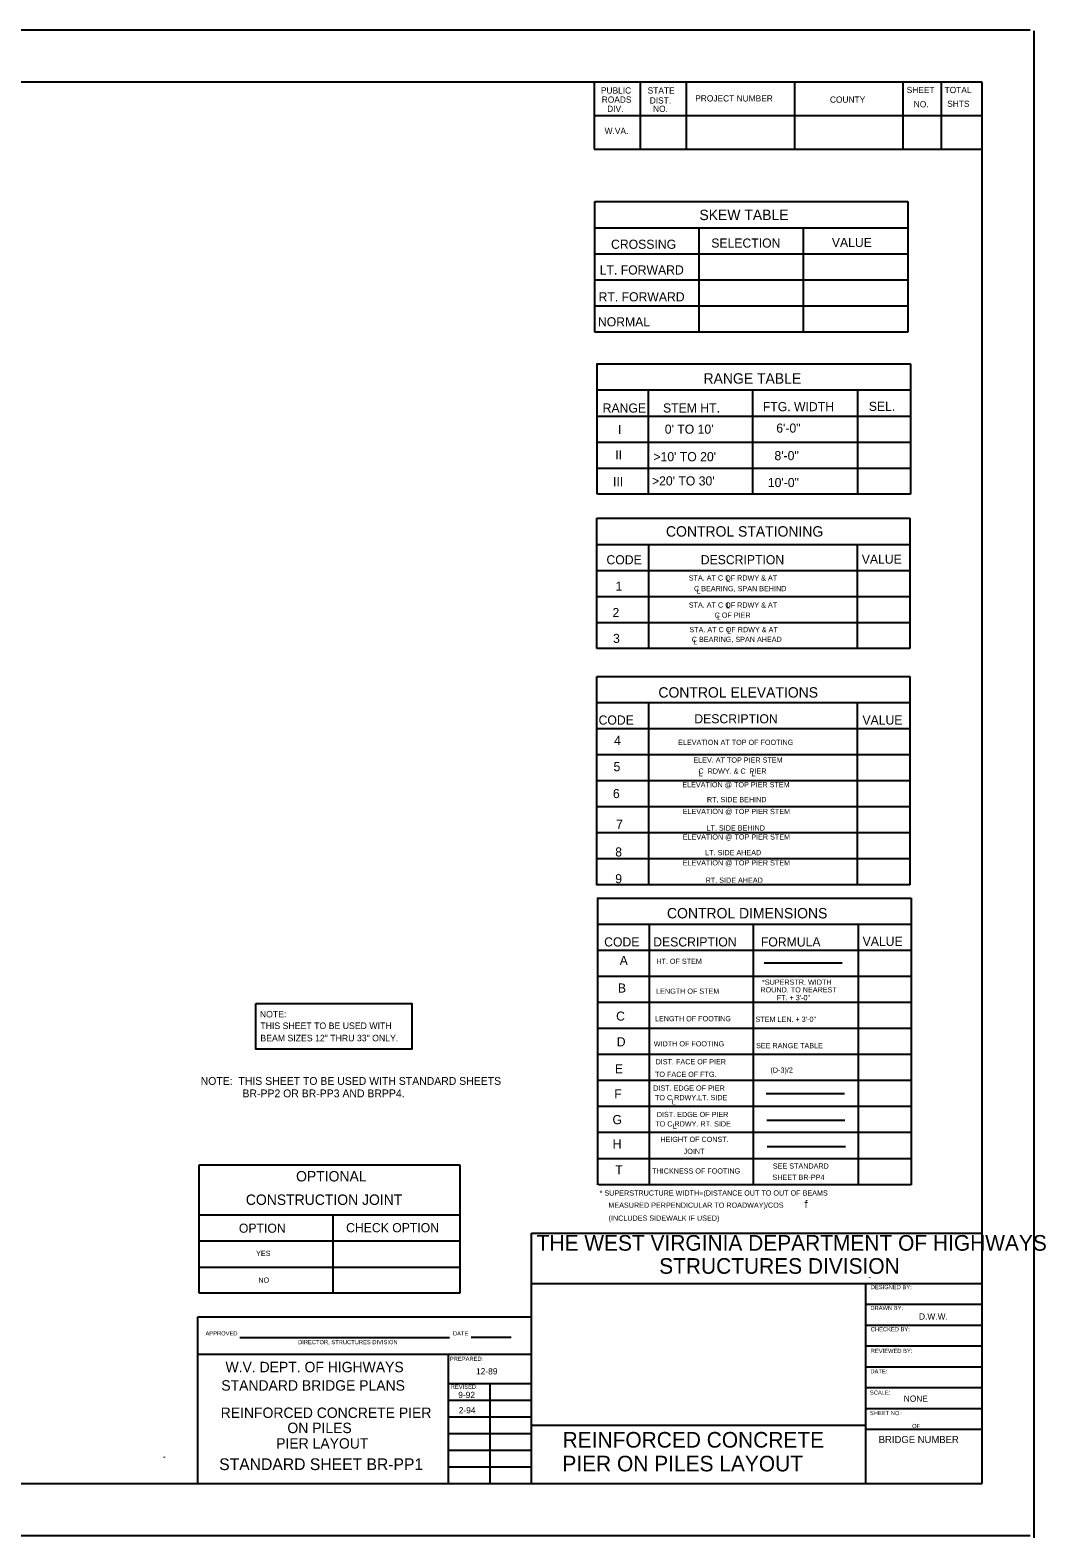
# Model space of a CAD drawing. Extents: x 1.6 to 6.29, y 2.8 to 7.08.
# Drawn here: x 4.663 to 6.287, y 4.671 to 7.081 of the extents above; entities that cross this region are included whole.
import ezdxf

# ---------------------------------------------------------------- set-up
doc = ezdxf.new("R2010")
doc.units = 0
doc.layers.add('Level 1', color=7, linetype='Continuous')
doc.layers.add('Level 5', color=7, linetype='Continuous')

msp = doc.modelspace()

# ---------------------------------------------------------------- linework, layer by layer
at = {"layer": 'Level 1'}
for p, q in [((6.2614, 7.0813), (2.3914, 7.0813)), ((6.2681, 4.6712), (6.2681, 7.0801)), ((6.1848, 6.998), (2.5581, 6.998)), ((5.5648, 6.998), (5.5648, 6.8913)), ((5.6381, 6.998), (5.6381, 6.8913)), ((5.7114, 6.998), (5.7114, 6.8913)), ((5.8847, 6.998), (5.8847, 6.8913)), ((6.0581, 6.998), (6.0581, 6.8913)), ((6.1194, 6.998), (6.1194, 6.8913)), ((6.1848, 4.758), (6.1848, 6.998)), ((5.5648, 6.9447), (6.1848, 6.9447)), ((5.5648, 6.8913), (6.1848, 6.8913)), ((5.5658, 6.5988), (5.5658, 6.8072)), ((5.5658, 6.8072), (6.0658, 6.8072)), ((6.0658, 6.8072), (6.0658, 6.5988)), ((5.5658, 6.7655), (6.0658, 6.7655)), ((5.7325, 6.5988), (5.7325, 6.7662)), ((5.8992, 6.5988), (5.8992, 6.7652)), ((5.5658, 6.7238), (6.0658, 6.7238)), ((5.5658, 6.6822), (6.0658, 6.6822)), ((5.5658, 6.6405), (6.0658, 6.6405)), ((6.0658, 6.5988), (5.5658, 6.5988)), ((5.5681, 6.5478), (6.0681, 6.5478)), ((5.5692, 6.3397), (5.5692, 6.548)), ((5.57, 6.5478), (6.07, 6.5478)), ((6.07, 6.5478), (6.07, 6.3395)), ((5.57, 6.5062), (6.07, 6.5062)), ((5.6515, 6.3397), (5.6515, 6.5061)), ((5.8182, 6.3403), (5.8182, 6.5066)), ((5.9859, 6.3397), (5.9859, 6.5061)), ((5.57, 6.4645), (6.07, 6.4645)), ((5.57, 6.4228), (6.07, 6.4228)), ((5.57, 6.3812), (6.07, 6.3812)), ((6.0701, 6.3394), (5.5701, 6.3394)), ((5.5688, 6.0927), (5.5688, 6.301)), ((5.5689, 6.301), (6.0689, 6.301)), ((6.0689, 6.301), (6.0689, 6.0927)), ((5.5689, 6.2593), (6.0689, 6.2593)), ((5.6522, 6.0927), (5.6522, 6.2592)), ((5.9855, 6.0927), (5.9855, 6.2592)), ((5.5689, 6.2177), (6.0689, 6.2177)), ((5.5689, 6.176), (6.0689, 6.176)), ((5.5689, 6.1343), (6.0689, 6.1343)), ((6.0689, 6.0927), (5.5689, 6.0927)), ((5.5689, 6.0483), (6.0689, 6.0483)), ((5.5689, 5.7146), (5.5689, 6.0483)), ((6.0689, 6.0483), (6.0689, 5.7151)), ((5.5689, 6.0067), (6.0689, 6.0067)), ((5.6522, 5.7146), (5.6522, 6.0067)), ((5.9856, 5.7146), (5.9856, 6.0067)), ((5.5689, 5.965), (6.0689, 5.965)), ((5.5689, 5.9233), (6.0689, 5.9233)), ((5.5689, 5.8817), (6.0689, 5.8817)), ((6.0689, 5.84), (5.5689, 5.84)), ((6.0689, 5.7983), (5.5689, 5.7983)), ((6.0689, 5.7567), (5.5689, 5.7567)), ((6.0689, 5.715), (5.5689, 5.715)), ((5.5693, 5.694), (6.0693, 5.694)), ((5.5704, 5.2356), (5.5704, 5.6942)), ((5.5713, 5.694), (6.0713, 5.694)), ((6.0713, 5.694), (6.0713, 5.2356)), ((5.5713, 5.6523), (6.0713, 5.6523)), ((5.6528, 5.2356), (5.6528, 5.6522)), ((5.8194, 5.2356), (5.8194, 5.6528)), ((5.9872, 5.2356), (5.9872, 5.6522)), ((5.5713, 5.6107), (6.0713, 5.6107)), ((5.5713, 5.569), (6.0713, 5.569)), ((5.5713, 5.5273), (6.0713, 5.5273)), ((6.0713, 5.4856), (5.5713, 5.4856)), ((6.0713, 5.4439), (5.5713, 5.4439)), ((6.0713, 5.4022), (5.5713, 5.4022)), ((6.0713, 5.3606), (5.5713, 5.3606)), ((6.0713, 5.3189), (5.5713, 5.3189)), ((4.9333, 5.2677), (5.3499, 5.2677)), ((4.9333, 5.0623), (4.9333, 5.2677)), ((5.3499, 5.2677), (5.3499, 5.0623)), ((6.0713, 5.2772), (5.5713, 5.2772)), ((6.0713, 5.2356), (5.5713, 5.2356)), ((4.9333, 5.1873), (5.3499, 5.1873)), ((5.1476, 5.062), (5.1476, 5.187)), ((5.4647, 4.758), (5.4647, 5.158)), ((5.4647, 5.158), (6.1848, 5.158)), ((4.9333, 5.1457), (5.3499, 5.1457)), ((4.9333, 5.104), (5.3499, 5.104)), ((6.0054, 5.0873), (6.0054, 5.088)), ((5.3499, 5.0623), (4.9333, 5.0623)), ((5.4647, 5.078), (6.1848, 5.078)), ((5.9981, 5.078), (5.9981, 4.758)), ((5.9981, 5.0447), (6.1848, 5.0447)), ((4.9314, 4.758), (4.9314, 5.0247)), ((4.9314, 5.0247), (5.4647, 5.0247)), ((4.9985, 4.9915), (5.3332, 4.9915)), ((5.3679, 4.992), (5.4321, 4.992)), ((5.9981, 5.0113), (6.1848, 5.0113)), ((5.9981, 4.978), (6.1848, 4.978)), ((4.9314, 4.9647), (5.4647, 4.9647)), ((5.3314, 4.9647), (5.3314, 4.758)), ((5.9981, 4.9447), (6.1848, 4.9447)), ((5.3314, 4.918), (5.4647, 4.918)), ((5.3981, 4.9187), (5.3981, 4.758)), ((5.9981, 4.9113), (6.1848, 4.9113)), ((5.3314, 4.8913), (5.4647, 4.8913)), ((5.9981, 4.878), (6.1848, 4.878)), ((5.3314, 4.8647), (5.4647, 4.8647)), ((5.4647, 4.8513), (5.9981, 4.8513)), ((5.9981, 4.8447), (6.1848, 4.8447)), ((5.3314, 4.838), (5.4647, 4.838)), ((4.8775, 4.8006), (4.8775, 4.7995)), ((5.3314, 4.8113), (5.4647, 4.8113)), ((5.3314, 4.7847), (5.4647, 4.7847)), ((2.5581, 4.758), (6.1848, 4.758)), ((2.5581, 4.758), (5.4647, 4.758)), ((6.1848, 4.758), (6.1848, 4.758)), ((2.3914, 4.6747), (6.2614, 4.6747))]:
    msp.add_line(p, q, dxfattribs=at)
msp.add_lwpolyline([(5.0241, 5.5255), (5.2733, 5.5255), (5.2733, 5.4523), (5.0241, 5.4523)], close=True, dxfattribs=at)
at = {"layer": 'Level 5'}
for p, q in [((5.8362, 5.5906), (5.9612, 5.5906)), ((5.8397, 5.3816), (5.9647, 5.3816)), ((5.8404, 5.3389), (5.9654, 5.3389)), ((5.8412, 5.2967), (5.9662, 5.2967))]:
    msp.add_line(p, q, dxfattribs=at)

# ---------------------------------------------------------------- texts
at = {"layer": 'Level 1'}
for s, height, p in [('PUBLIC', 0.01, (5.5754, 6.98)), ('STATE', 0.01, (5.6501, 6.98)), ('SHEET', 0.01, (6.0641, 6.9807)), ('TOTAL', 0.01, (6.1247, 6.9807)), ('ROADS', 0.01, (5.5767, 6.9653)), ('DIST.', 0.01, (5.6534, 6.964)), ('PROJECT NUMBER', 0.01, (5.7261, 6.9673)), ('COUNTY', 0.01, (5.9414, 6.9653)), ('NO.', 0.01, (6.0754, 6.958)), ('SHTS', 0.01, (6.1288, 6.9587)), ('DIV.', 0.01, (5.5854, 6.9507)), ('NO.', 0.01, (5.6587, 6.9507)), ('W.VA.', 0.01, (5.5814, 6.9153)), ('SKEW TABLE', 0.01667, (5.7328, 6.7777)), ('SELECTION', 0.01458, (5.7518, 6.7337)), ('VALUE', 0.01458, (5.9445, 6.7347)), ('CROSSING', 0.01458, (5.5916, 6.7318)), ('LT. FORWARD', 0.014584, (5.5735, 6.6907)), ('RT. FORWARD', 0.014584, (5.5716, 6.6478)), ('NORMAL', 0.01458, (5.5706, 6.6078)), ('RANGE TABLE', 0.016666, (5.7394, 6.5162)), ('RANGE', 0.01458, (5.5782, 6.47)), ('STEM HT. ', 0.01458, (5.6747, 6.4701)), ('FTG. WIDTH', 0.01458, (5.8342, 6.4722)), ('SEL.', 0.01458, (6.0036, 6.4727)), ('I', 0.0146, (5.6026, 6.4355)), ("0' TO 10'", 0.01458, (5.6775, 6.4362)), ('6\'-0"', 0.01458, (5.8557, 6.4379)), ('II', 0.01458, (5.5983, 6.3952)), (">10' TO 20'", 0.014584, (5.6593, 6.3922)), ('8\'-0"', 0.01458, (5.8528, 6.3939)), ('III', 0.01458, (5.5947, 6.3522)), (">20' TO 30'", 0.014584, (5.657, 6.3535)), ('10\'-0"', 0.01458, (5.8422, 6.3509)), ('CONTROL STATIONING', 0.016666, (5.6794, 6.2717)), ('VALUE', 0.01458, (5.9923, 6.2284)), ('CODE', 0.01458, (5.5843, 6.2274)), ('DESCRIPTION', 0.014584, (5.735, 6.2275)), ('1', 0.0146, (5.5987, 6.1852)), ('STA. AT C OF RDWY & AT', 0.008333, (5.7158, 6.2015)), ('L', 0.00833, (5.7755, 6.1997)), ('C BEARING, SPAN BEHIND', 0.008333, (5.7242, 6.1845)), ('L', 0.00833, (5.7283, 6.1804)), ('2', 0.0146, (5.5939, 6.143)), ('STA. AT C OF RDWY & AT', 0.008333, (5.7158, 6.1582)), ('C OF PIER', 0.00833, (5.7572, 6.142)), ('L', 0.00833, (5.761, 6.1382)), ('L', 0.00833, (5.7757, 6.157)), ('STA. AT C OF RDWY & AT', 0.008333, (5.7168, 6.1189)), ('L', 0.00833, (5.7769, 6.1168)), ('3', 0.0146, (5.5948, 6.1017)), ('C BEARING, SPAN AHEAD', 0.008333, (5.7206, 6.1033)), ('L', 0.00833, (5.7235, 6.0988)), ('CONTROL ELEVATIONS', 0.016666, (5.6673, 6.0143)), ('CODE', 0.01458, (5.5717, 5.9712)), ('DESCRIPTION ', 0.014584, (5.7247, 5.9732)), ('VALUE', 0.01458, (5.9934, 5.9712)), ('4', 0.0146, (5.5965, 5.9387)), ('ELEVATION AT TOP OF FOOTING', 0.008333, (5.6988, 5.9387)), ('5', 0.0146, (5.5956, 5.8967)), ('ELEV. AT TOP PIER STEM', 0.008333, (5.7232, 5.9104)), ('6', 0.0146, (5.5946, 5.8537)), ('CONTROL DIMENSIONS', 0.016666, (5.681, 5.6614)), ('CODE', 0.01458, (5.5806, 5.6165)), ('DESCRIPTION', 0.014584, (5.659, 5.6165)), ('FORMULA', 0.01458, (5.8311, 5.6165)), ('VALUE', 0.01458, (5.9937, 5.6175)), ('A', 0.0146, (5.6054, 5.5868)), ('HT. OF STEM ', 0.008333, (5.6639, 5.5887)), ('B', 0.0146, (5.6026, 5.5428)), ('LENGTH OF STEM', 0.008333, (5.6637, 5.5409)), ('ROUND. TO NEAREST', 0.008333, (5.8303, 5.5431)), ('*SUPERSTR. WIDTH', 0.008333, (5.8329, 5.5553)), ('FT. + 3\'-0"', 0.008333, (5.8564, 5.5305)), ('NOTE:', 0.01042, (5.0302, 5.5031)), ('C', 0.0146, (5.5997, 5.4979)), ('LENGTH OF FOOTING', 0.008333, (5.6618, 5.497)), ('STEM LEN. + 3\'-0"', 0.008333, (5.8225, 5.496)), ('THIS SHEET TO BE USED WITH', 0.010417, (5.0311, 5.4846)), ('BEAM SIZES 12" THRU 33" ONLY.', 0.010417, (5.0311, 5.4649)), ('D', 0.0146, (5.6007, 5.4568)), ('WIDTH OF FOOTING', 0.008333, (5.6599, 5.4568)), ('SEE RANGE TABLE', 0.008333, (5.8234, 5.4539)), ('E', 0.0146, (5.5977, 5.4137)), ('DIST. FACE OF PIER', 0.008333, (5.6628, 5.4281)), ('(D-3)/2', 0.00833, (5.8464, 5.4147)), ('NOTE:  THIS SHEET TO BE USED WITH STANDARD SHEETS', 0.0125, (4.9357, 5.3953)), ('TO FACE OF FTG.', 0.008333, (5.6618, 5.408)), ('BR-PP2 OR BR-PP3 AND BRPP4.', 0.0125, (5.0025, 5.3754)), ('F', 0.0146, (5.5968, 5.3736)), ('DIST. EDGE OF PIER', 0.008333, (5.659, 5.386)), ('TO C RDWY.LT. SIDE', 0.008333, (5.6618, 5.3708)), ('DIST. EDGE OF PIER', 0.008333, (5.6647, 5.3438)), ('L', 0.00833, (5.6886, 5.364)), ('G', 0.0146, (5.5939, 5.3325)), ('TO C RDWY. RT. SIDE', 0.008333, (5.6623, 5.3288)), ('L', 0.00833, (5.6902, 5.325)), ('H', 0.0146, (5.5942, 5.2935)), ('HEIGHT OF CONST.', 0.008333, (5.6703, 5.304)), ('JOINT', 0.00833, (5.7077, 5.2849)), ('OPTIONAL', 0.01667, (5.0882, 5.2409)), ('T', 0.0146, (5.5984, 5.2521)), ('THICKNESS OF FOOTING', 0.008333, (5.6573, 5.2535)), ('SEE STANDARD', 0.008333, (5.8502, 5.2614)), ('SHEET BR-PP4', 0.008333, (5.8496, 5.2434)), ('CONSTRUCTION JOINT', 0.016666, (5.0079, 5.2034)), ('f ', 0.0125, (5.901, 5.1982)), ('OPTION', 0.01458, (4.9968, 5.1589)), ('CHECK OPTION', 0.014584, (5.1682, 5.1597)), ('THE WEST VIRGINIA DEPARTMENT OF HIGHWAYS', 0.025, (5.4727, 5.1302)), ('YES', 0.00833, (5.0243, 5.1218)), ('STRUCTURES DIVISION', 0.025, (5.6685, 5.0933)), ('NO', 0.00833, (5.0279, 5.079)), ('DESIGNED BY:', 0.006668, (6.0067, 5.0687)), ('DRAWN BY:', 0.00667, (6.0061, 5.0353)), ('D.W.W.', 0.01, (6.0838, 5.02)), ('APPROVED', 0.00667, (4.9434, 4.9947)), ('DATE', 0.00667, (5.3388, 4.9947)), ('CHECKED BY:', 0.006668, (6.0067, 5.0013)), ('DIRECTOR, STRUCTURES DIVISION', 0.006668, (5.0914, 4.9807)), ('REVIEWED BY:', 0.006668, (6.0067, 4.9667)), ('W.V. DEPT. OF HIGHWAYS', 0.016666, (4.9754, 4.9359)), ('PREPARED:', 0.00667, (5.3341, 4.954)), ('12-89', 0.01, (5.3758, 4.9324)), ('STANDARD BRIDGE PLANS', 0.016666, (4.9687, 4.9065)), ('DATE:', 0.00667, (6.0061, 4.934)), ('REVISED:', 0.00667, (5.3354, 4.9093)), ('9-92', 0.01, (5.3474, 4.8946)), ('SCALE:', 0.00667, (6.0054, 4.9)), ('NONE', 0.01, (6.0594, 4.8887)), ('REINFORCED CONCRETE PIER', 0.016666, (4.9677, 4.8628)), ('2-94', 0.01, (5.3482, 4.8701)), ('SHEET NO.:', 0.00667, (6.0054, 4.8673)), ('ON PILES', 0.01667, (5.0743, 4.8386)), ('OF', 0.00667, (6.0728, 4.8467)), ('PIER LAYOUT', 0.016666, (5.0564, 4.8138)), ('REINFORCED CONCRETE', 0.025, (5.5142, 4.8154)), ('BRIDGE NUMBER', 0.011332, (6.0194, 4.8227)), ('STANDARD SHEET BR-PP1', 0.01875, (4.9653, 4.7795)), ('PIER ON PILES LAYOUT', 0.025, (5.5138, 4.7774))]:
    msp.add_text(s, height=height, dxfattribs=at).set_placement(p)
at = {"layer": 'Level 5'}
for s, height, p in [('C  RDWY. & C  PIER', 0.008333, (5.7313, 5.8927)), ('L', 0.00833, (5.7319, 5.8886)), ('L', 0.00833, (5.8161, 5.8886)), ('ELEVATION @ TOP PIER STEM', 0.008333, (5.7055, 5.871)), ('ELEVATION @ TOP PIER STEM', 0.008333, (5.7062, 5.8282)), ('RT. SIDE BEHIND', 0.008333, (5.7448, 5.8472)), ('7', 0.0146, (5.5996, 5.8045)), ('LT. SIDE BEHIND', 0.008333, (5.7442, 5.8018)), ('ELEVATION @ TOP PIER STEM', 0.008333, (5.7062, 5.7875)), ('8', 0.0146, (5.5983, 5.7603)), ('LT. SIDE AHEAD', 0.008333, (5.7421, 5.7624)), ('ELEVATION @ TOP PIER STEM', 0.008333, (5.7062, 5.7461)), ('9', 0.0146, (5.5983, 5.7176)), ('RT. SIDE AHEAD', 0.008333, (5.7428, 5.7183)), ('* SUPERSTRUCTURE WIDTH=(DISTANCE OUT TO OUT OF BEAMS', 0.008333, (5.5733, 5.2183)), ('MEASURED PERPENDICULAR TO ROADWAY)/COS ', 0.008333, (5.5873, 5.1988)), ('(INCLUDES SIDEWALK IF USED)', 0.008333, (5.5876, 5.1781))]:
    msp.add_text(s, height=height, dxfattribs=at).set_placement(p)

doc.saveas('drawing.dxf')
